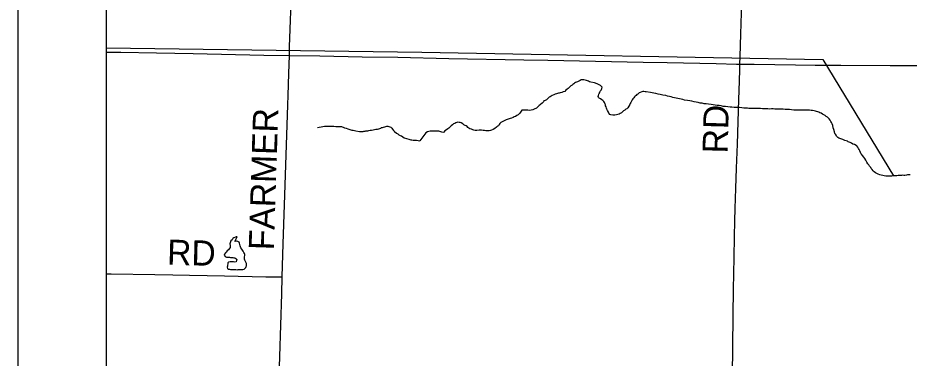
# Model space of a CAD drawing. Extents: x 2.1 to 73.9, y 4 to 26.
# Drawn here: x 41.859 to 42.866, y 24.066 to 24.45 of the extents above; entities that cross this region are included whole.
import ezdxf

# ---------------------------------------------------------------- set-up
doc = ezdxf.new("R2010")
doc.units = 0
for name, color, linetype in [('GM_X_County_Road', 7, 'Continuous'), ('GM_X_County_Road_Text', 7, 'Continuous'), ('GM_X_Minor_Lake', 7, 'Continuous'), ('GM_X_Minor_River', 7, 'Continuous'), ('GM_X_Township_Road', 7, 'Continuous'), ('GM_X_Township_Road_Text', 7, 'Continuous'), ('SH_Data', 7, 'Continuous')]:
    doc.layers.add(name, color=color, linetype=linetype)

msp = doc.modelspace()

# ---------------------------------------------------------------- linework, layer by layer
at = {"layer": 'GM_X_County_Road'}
for points in [[(42.1655, 24.4075), (42.1658, 24.4171), (42.1681, 24.4877), (42.1694, 24.5296), (42.17, 24.5508), (42.1704, 24.5638), (42.1708, 24.5793), (42.1721, 24.6176), (42.1738, 24.6704), (42.1758, 24.7347), (42.1765, 24.758), (42.1782, 24.8099), (42.179, 24.8335), (42.1798, 24.8571), (42.1805, 24.8804), (42.1815, 24.9051)], [(41.9585, 24.4114), (41.9748, 24.4111), (42.0152, 24.4103), (42.0566, 24.4096), (42.1367, 24.4079), (42.1655, 24.4075)], [(42.1574, 24.1573), (42.1586, 24.1947), (42.16, 24.2388), (42.1615, 24.2835), (42.1638, 24.3519), (42.164, 24.3622), (42.1649, 24.3873), (42.1655, 24.4075)], [(42.1655, 24.4075), (42.1998, 24.407), (42.2477, 24.4061), (42.2881, 24.4054), (42.3456, 24.4042), (42.4304, 24.4026), (42.4575, 24.4021), (42.5116, 24.401), (42.5653, 24.3999), (42.5924, 24.3995), (42.648, 24.3983), (42.671, 24.3978), (42.6747, 24.3978)], [(42.6747, 24.3978), (42.6909, 24.3975), (42.7375, 24.3969), (42.7599, 24.3967), (42.7888, 24.3967), (42.8445, 24.3963), (42.8746, 24.3962), (42.9104, 24.3959), (42.9561, 24.3954), (42.9819, 24.3952), (43.026, 24.395), (43.0534, 24.3948), (43.0959, 24.3944), (43.1177, 24.3942), (43.1618, 24.3936), (43.1649, 24.3935)], [(42.1493, 23.9037), (42.1497, 23.92), (42.1506, 23.9468), (42.1527, 24.0114), (42.1534, 24.0319), (42.1557, 24.1027), (42.1569, 24.1381), (42.1574, 24.1573)]]:
    msp.add_lwpolyline(points, dxfattribs=at)
at = {"layer": 'GM_X_Minor_Lake'}
msp.add_line((42.104, 24.1975), (42.1063, 24.2027), dxfattribs=at)
msp.add_lwpolyline([(42.1063, 24.2027), (42.1055, 24.2026), (42.1044, 24.2021), (42.1028, 24.2017), (42.1017, 24.2008), (42.1007, 24.1993), (42.0995, 24.198), (42.0989, 24.1971), (42.0985, 24.1958), (42.0982, 24.1947), (42.0986, 24.1928), (42.0987, 24.1916), (42.0985, 24.1905), (42.0973, 24.189), (42.0965, 24.1881), (42.0953, 24.1868), (42.0939, 24.1853), (42.0932, 24.1844), (42.092, 24.1829), (42.0919, 24.1818), (42.093, 24.1804), (42.0943, 24.1798), (42.0955, 24.1796), (42.0968, 24.1795), (42.0979, 24.1795), (42.0991, 24.1794), (42.1002, 24.1794), (42.1014, 24.1794), (42.1027, 24.1791), (42.1038, 24.1789), (42.1051, 24.1781), (42.106, 24.177), (42.1056, 24.1758), (42.1052, 24.1743), (42.1039, 24.174), (42.1022, 24.1744), (42.1008, 24.1745), (42.0997, 24.1745), (42.0984, 24.1745), (42.0968, 24.174), (42.096, 24.1731), (42.0958, 24.1721), (42.0956, 24.1708), (42.0955, 24.1697), (42.0953, 24.1682), (42.0955, 24.1668), (42.0964, 24.1662), (42.0977, 24.166), (42.099, 24.1658), (42.1002, 24.1657), (42.1013, 24.1657), (42.1026, 24.1657), (42.104, 24.1656), (42.1051, 24.1656), (42.1064, 24.1655), (42.1076, 24.1657), (42.1087, 24.1657), (42.1102, 24.1656), (42.1114, 24.1656), (42.1129, 24.1659), (42.1143, 24.1661), (42.115, 24.167), (42.1162, 24.1681), (42.1168, 24.169), (42.117, 24.17), (42.1171, 24.1709), (42.1169, 24.1726), (42.1164, 24.174), (42.1159, 24.1749), (42.1152, 24.1763), (42.1148, 24.1774), (42.1147, 24.179), (42.1149, 24.1801), (42.1151, 24.1814), (42.115, 24.1826), (42.1148, 24.1837), (42.1141, 24.1851), (42.1132, 24.1864), (42.1125, 24.1874), (42.1117, 24.1887), (42.1108, 24.1901), (42.1101, 24.1913), (42.11, 24.1924), (42.1091, 24.1955), (42.1086, 24.1966), (42.1071, 24.1974), (42.1056, 24.1977), (42.1046, 24.1977), (42.104, 24.1975)], dxfattribs=at)
msp.add_lwpolyline([(42.1063, 24.2027), (42.1055, 24.2026), (42.1044, 24.2021), (42.1028, 24.2017), (42.1017, 24.2008), (42.1007, 24.1993), (42.0995, 24.198), (42.0989, 24.1971), (42.0985, 24.1958), (42.0982, 24.1947), (42.0986, 24.1928), (42.0987, 24.1916), (42.0985, 24.1905), (42.0973, 24.189), (42.0965, 24.1881), (42.0953, 24.1868), (42.0939, 24.1853), (42.0932, 24.1844), (42.092, 24.1829), (42.0919, 24.1818), (42.093, 24.1804), (42.0943, 24.1798), (42.0955, 24.1796), (42.0968, 24.1795), (42.0979, 24.1795), (42.0991, 24.1794), (42.1002, 24.1794), (42.1014, 24.1794), (42.1027, 24.1791), (42.1038, 24.1789), (42.1051, 24.1781), (42.106, 24.177), (42.1056, 24.1758), (42.1052, 24.1743), (42.1039, 24.174), (42.1022, 24.1744), (42.1008, 24.1745), (42.0997, 24.1745), (42.0984, 24.1745), (42.0968, 24.174), (42.096, 24.1731), (42.0958, 24.1721), (42.0956, 24.1708), (42.0955, 24.1697), (42.0953, 24.1682), (42.0955, 24.1668), (42.0964, 24.1662), (42.0977, 24.166), (42.099, 24.1658), (42.1002, 24.1657), (42.1013, 24.1657), (42.1026, 24.1657), (42.104, 24.1656), (42.1051, 24.1656), (42.1064, 24.1655), (42.1076, 24.1657), (42.1087, 24.1657), (42.1102, 24.1656), (42.1114, 24.1656), (42.1129, 24.1659), (42.1143, 24.1661), (42.115, 24.167), (42.1162, 24.1681), (42.1168, 24.169), (42.117, 24.17), (42.1171, 24.1709), (42.1169, 24.1726), (42.1164, 24.174), (42.1159, 24.1749), (42.1152, 24.1763), (42.1148, 24.1774), (42.1147, 24.179), (42.1149, 24.1801), (42.1151, 24.1814), (42.115, 24.1826), (42.1148, 24.1837), (42.1141, 24.1851), (42.1132, 24.1864), (42.1125, 24.1874), (42.1117, 24.1887), (42.1108, 24.1901), (42.1101, 24.1913), (42.11, 24.1924), (42.1091, 24.1955), (42.1086, 24.1966), (42.1071, 24.1974), (42.1056, 24.1977), (42.1046, 24.1977), (42.104, 24.1975)], dxfattribs=at)
at = {"layer": 'GM_X_Minor_River'}
msp.add_line((41.9585, 24.4163), (42.3154, 24.4112), dxfattribs=at)
for points in [[(42.3154, 24.4112), (42.7684, 24.4028), (42.8485, 24.2714)], [(42.5216, 24.3544), (42.5208, 24.3556), (42.5197, 24.3566), (42.5186, 24.3575), (42.5171, 24.3585), (42.5157, 24.3593), (42.5148, 24.3599), (42.5146, 24.361), (42.5148, 24.3621), (42.5154, 24.3637), (42.5158, 24.3646), (42.5164, 24.3657), (42.5168, 24.3671), (42.5178, 24.3682), (42.5182, 24.3691), (42.5186, 24.3703), (42.5192, 24.3716), (42.5182, 24.3725), (42.5173, 24.3735), (42.5158, 24.3743), (42.5149, 24.3747), (42.5135, 24.3753), (42.5124, 24.3759), (42.5115, 24.3763), (42.5105, 24.3765), (42.5061, 24.3773), (42.5048, 24.3779), (42.5035, 24.3783), (42.5024, 24.3787), (42.5012, 24.3791), (42.4997, 24.3797), (42.4984, 24.3799), (42.4972, 24.3801), (42.4963, 24.3801), (42.4953, 24.3799), (42.4942, 24.3794), (42.4927, 24.3786), (42.4911, 24.3779), (42.489, 24.3768), (42.4879, 24.3761), (42.4869, 24.3755), (42.4859, 24.3748), (42.485, 24.3738), (42.4838, 24.3731), (42.4829, 24.3723), (42.4819, 24.3712), (42.4805, 24.3703), (42.4794, 24.3694), (42.478, 24.3682), (42.4767, 24.3669), (42.475, 24.3664), (42.4734, 24.3657), (42.4715, 24.3653), (42.4706, 24.3649), (42.4696, 24.3648), (42.4685, 24.3644), (42.4673, 24.364), (42.466, 24.3637), (42.4646, 24.3631), (42.4627, 24.3624), (42.4616, 24.3615), (42.4602, 24.3609), (42.4593, 24.3604), (42.4579, 24.3593), (42.457, 24.3581), (42.456, 24.3574), (42.4545, 24.3568), (42.4533, 24.3563), (42.4527, 24.3553), (42.4514, 24.3538), (42.4498, 24.3524), (42.4489, 24.3516), (42.4479, 24.3509), (42.4466, 24.3497), (42.4448, 24.3481), (42.4423, 24.347), (42.4406, 24.3462), (42.4389, 24.3459), (42.437, 24.3455), (42.4349, 24.3456), (42.4328, 24.3456), (42.4309, 24.3458), (42.4296, 24.3458), (42.4284, 24.3457), (42.4269, 24.3434), (42.4255, 24.3419), (42.4242, 24.3406), (42.4226, 24.3397), (42.4211, 24.3387), (42.4197, 24.338), (42.4184, 24.3373), (42.4167, 24.3367), (42.415, 24.3362), (42.4129, 24.3357), (42.4106, 24.3347), (42.4081, 24.3338), (42.4062, 24.3327), (42.4046, 24.3318), (42.4035, 24.3307), (42.4025, 24.3295), (42.4017, 24.3282)], [(42.7023, 24.3474), (42.7004, 24.3474), (42.6981, 24.3475), (42.6957, 24.3475), (42.6924, 24.3476), (42.6864, 24.3477), (42.6848, 24.3477), (42.6833, 24.3479), (42.6814, 24.3479), (42.6793, 24.3481), (42.677, 24.3484), (42.6744, 24.3486), (42.6719, 24.3488), (42.6683, 24.3489), (42.6658, 24.3491), (42.6636, 24.3492), (42.6611, 24.3494), (42.6586, 24.3498), (42.656, 24.35), (42.6537, 24.3505), (42.6514, 24.3509), (42.6491, 24.3511), (42.6467, 24.3515), (42.6444, 24.3519), (42.6421, 24.3523), (42.6391, 24.3526), (42.6368, 24.3528), (42.6345, 24.353), (42.632, 24.3535), (42.6298, 24.3537), (42.6275, 24.3543), (42.6252, 24.3547), (42.6229, 24.3551), (42.6205, 24.3557), (42.618, 24.3561), (42.6154, 24.3568), (42.6123, 24.3572), (42.6102, 24.3576), (42.6083, 24.358), (42.6065, 24.3584), (42.6046, 24.3588), (42.6027, 24.3592), (42.6008, 24.3596), (42.5989, 24.3602), (42.597, 24.3607), (42.5951, 24.3611), (42.593, 24.3615), (42.5909, 24.3621), (42.5877, 24.3627), (42.5848, 24.3633), (42.5822, 24.3639), (42.5797, 24.3645), (42.5776, 24.365), (42.5756, 24.3654), (42.5737, 24.3658), (42.5687, 24.3666), (42.5676, 24.3666), (42.5663, 24.3667), (42.5651, 24.3667), (42.5638, 24.3663), (42.5621, 24.3658), (42.5609, 24.3652), (42.5592, 24.3639), (42.5582, 24.3634), (42.5574, 24.3624), (42.5563, 24.3617), (42.5555, 24.3607), (42.5547, 24.3596), (42.5538, 24.3585), (42.553, 24.3574), (42.5522, 24.3559), (42.5514, 24.3545), (42.5508, 24.3534), (42.5502, 24.3523), (42.5491, 24.3502), (42.5479, 24.3483), (42.5469, 24.3474), (42.5458, 24.3467), (42.5446, 24.3457), (42.5431, 24.3448), (42.5419, 24.3439), (42.5408, 24.3427), (42.5394, 24.342), (42.5383, 24.3413), (42.5368, 24.3407), (42.5354, 24.3404), (42.5333, 24.3402), (42.5312, 24.3402), (42.5289, 24.3405), (42.5278, 24.3409), (42.5267, 24.3424), (42.5261, 24.3435), (42.525, 24.3453), (42.5243, 24.347), (42.5239, 24.3479), (42.5236, 24.3495), (42.523, 24.3506), (42.5229, 24.3516), (42.5225, 24.3525), (42.5219, 24.3535), (42.5216, 24.3544)], [(42.8485, 24.2714), (42.8472, 24.2714), (42.8462, 24.2712), (42.8453, 24.2712), (42.8441, 24.2713), (42.8428, 24.2711), (42.8413, 24.2711), (42.8398, 24.2713), (42.838, 24.2715), (42.8329, 24.2728), (42.8312, 24.2734), (42.8297, 24.2741), (42.8282, 24.2751), (42.8267, 24.2759), (42.8254, 24.2773), (42.8243, 24.2786), (42.8233, 24.2798), (42.8226, 24.2811), (42.8213, 24.2824), (42.8204, 24.2838), (42.8194, 24.2851), (42.8183, 24.2869), (42.8172, 24.2892), (42.8159, 24.2911), (42.8148, 24.2926), (42.8135, 24.2945), (42.8124, 24.2959), (42.8116, 24.2968), (42.8111, 24.298), (42.8102, 24.2999), (42.8094, 24.3013), (42.8089, 24.3026), (42.8079, 24.3039), (42.807, 24.3053), (42.8061, 24.3059), (42.8042, 24.3068), (42.8025, 24.3074), (42.8008, 24.3084), (42.7993, 24.3092), (42.7983, 24.3096), (42.7972, 24.31), (42.7963, 24.3106), (42.7947, 24.3112), (42.7932, 24.3116), (42.7913, 24.3124), (42.7898, 24.3128), (42.7887, 24.3132), (42.7876, 24.3136), (42.7866, 24.314), (42.7853, 24.3149), (42.784, 24.3165), (42.7834, 24.3174), (42.7829, 24.3186), (42.7821, 24.3195), (42.7816, 24.3211), (42.7809, 24.3239), (42.7803, 24.3256), (42.7798, 24.3283), (42.7791, 24.3304), (42.7783, 24.3319), (42.7776, 24.3331), (42.7767, 24.3344), (42.7757, 24.3358), (42.7746, 24.3369), (42.7737, 24.3377), (42.7724, 24.3387), (42.771, 24.3397), (42.7697, 24.3404), (42.7682, 24.3412), (42.7665, 24.3422), (42.7652, 24.3428), (42.7641, 24.3434), (42.7627, 24.3438), (42.7614, 24.3442), (42.7601, 24.3446), (42.7586, 24.345), (42.7569, 24.3452), (42.7552, 24.3454), (42.7535, 24.3456), (42.7517, 24.3457), (42.7495, 24.3459), (42.7462, 24.3458), (42.7436, 24.3458), (42.7407, 24.3458), (42.7381, 24.3459), (42.7356, 24.3459), (42.7331, 24.3462), (42.7308, 24.3464), (42.7286, 24.3464), (42.7261, 24.3466), (42.7238, 24.3467), (42.7215, 24.3467), (42.7187, 24.347), (42.7166, 24.347), (42.7143, 24.347), (42.7124, 24.3471), (42.7103, 24.3471), (42.7084, 24.3469), (42.7063, 24.3471), (42.7044, 24.3474), (42.7023, 24.3474)], [(42.1971, 24.3263), (42.1992, 24.3267), (42.2015, 24.327), (42.2034, 24.3273), (42.2053, 24.3276), (42.2074, 24.3278), (42.2095, 24.3277), (42.212, 24.3276), (42.2139, 24.3276), (42.2158, 24.3275), (42.2181, 24.3274), (42.2203, 24.3274), (42.222, 24.3273), (42.2234, 24.3273), (42.2243, 24.3272), (42.2253, 24.3268), (42.2264, 24.3264), (42.2279, 24.3258), (42.2298, 24.3252), (42.2317, 24.3247), (42.2328, 24.3243), (42.2339, 24.3237), (42.235, 24.3235), (42.236, 24.3233), (42.2375, 24.323), (42.2392, 24.3228), (42.2407, 24.3222), (42.2449, 24.3218), (42.246, 24.3216), (42.2479, 24.3217), (42.2489, 24.3217), (42.2498, 24.3219), (42.251, 24.322), (42.2521, 24.3222), (42.2531, 24.3223), (42.254, 24.3225), (42.2552, 24.3227), (42.2569, 24.323), (42.2584, 24.3231), (42.2603, 24.3234), (42.2619, 24.3238), (42.2634, 24.3241), (42.2651, 24.3244), (42.2667, 24.3248), (42.2676, 24.3251), (42.2688, 24.3255), (42.2697, 24.326), (42.2709, 24.3263), (42.272, 24.3267), (42.2734, 24.327), (42.2747, 24.3274), (42.2757, 24.3275), (42.2766, 24.3275), (42.278, 24.3273), (42.2789, 24.3269), (42.28, 24.3264), (42.2813, 24.3253), (42.282, 24.3243), (42.2831, 24.3229), (42.2844, 24.3216), (42.2865, 24.3198), (42.288, 24.3188), (42.2893, 24.3178), (42.2906, 24.3172), (42.2923, 24.3166), (42.2937, 24.3156), (42.2954, 24.3146), (42.3007, 24.3129), (42.3026, 24.3123), (42.3041, 24.3122), (42.3056, 24.312), (42.3067, 24.3117), (42.3077, 24.3117), (42.3092, 24.3119), (42.313, 24.3111)], [(42.4017, 24.3282), (42.4007, 24.3275), (42.3996, 24.3264), (42.3977, 24.3249), (42.3959, 24.3238), (42.394, 24.3232), (42.3927, 24.3229), (42.3913, 24.3225), (42.39, 24.3223), (42.3889, 24.3224), (42.3877, 24.3224), (42.3862, 24.3226), (42.3847, 24.3228), (42.3826, 24.3232), (42.3801, 24.3231), (42.3773, 24.3229), (42.3756, 24.3229), (42.374, 24.3232), (42.3727, 24.3236), (42.3712, 24.3242), (42.3695, 24.3248), (42.3682, 24.3255), (42.3673, 24.3263), (42.3663, 24.3271), (42.3652, 24.3279), (42.3641, 24.3284), (42.3627, 24.329), (42.3616, 24.3302), (42.3597, 24.3314), (42.3586, 24.3318), (42.3573, 24.3318), (42.3559, 24.332), (42.3548, 24.3318), (42.3536, 24.3313), (42.3525, 24.3307), (42.3511, 24.3302), (42.3498, 24.3292), (42.3484, 24.3279), (42.3469, 24.3264), (42.3456, 24.3255), (42.3446, 24.3246), (42.3432, 24.3235), (42.3411, 24.3222), (42.34, 24.321), (42.3388, 24.3205), (42.3366, 24.3213), (42.3343, 24.3219), (42.332, 24.3219), (42.3297, 24.322), (42.3274, 24.322), (42.3259, 24.322), (42.3246, 24.3219), (42.3231, 24.3217), (42.3215, 24.3211), (42.3198, 24.3202), (42.313, 24.3111)], [(42.8674, 24.2728), (42.866, 24.2726), (42.8643, 24.2725), (42.863, 24.2723), (42.8613, 24.2721), (42.8599, 24.2721), (42.8586, 24.2722), (42.8573, 24.272), (42.8559, 24.272), (42.8546, 24.272), (42.8535, 24.2719), (42.8521, 24.2717), (42.8508, 24.2717), (42.8495, 24.2716), (42.8485, 24.2714)]]:
    msp.add_lwpolyline(points, dxfattribs=at)
at = {"layer": 'GM_X_Township_Road'}
for points in [[(42.6747, 24.3978), (42.675, 24.4064), (42.6758, 24.4316), (42.6773, 24.4801), (42.6778, 24.499), (42.6786, 24.5313), (42.6791, 24.5444), (42.6796, 24.5599), (42.6801, 24.5782), (42.6814, 24.6314), (42.6822, 24.6652), (42.6827, 24.6941), (42.6834, 24.7224), (42.6839, 24.7563), (42.6842, 24.769), (42.6843, 24.7852), (42.6845, 24.8044), (42.6847, 24.8249), (42.685, 24.8433), (42.6853, 24.8576), (42.6859, 24.889), (42.686, 24.9038)], [(42.6642, 23.8935), (42.6645, 23.9112), (42.6648, 23.9363), (42.6654, 23.9724), (42.6657, 23.9982), (42.6661, 24.0215), (42.6665, 24.0464), (42.6668, 24.0778), (42.6673, 24.1141), (42.6675, 24.1433), (42.6681, 24.1794), (42.6687, 24.2027), (42.6692, 24.2207), (42.6695, 24.2347), (42.6702, 24.2574), (42.6709, 24.2801), (42.6719, 24.3074), (42.6734, 24.3577), (42.6742, 24.3785), (42.6746, 24.3916), (42.6747, 24.3978)], [(41.9585, 24.1609), (41.9639, 24.1608), (42.0134, 24.1601), (42.0336, 24.1597), (42.0525, 24.1594), (42.0724, 24.1589), (42.092, 24.1586), (42.1389, 24.1576), (42.1574, 24.1573)]]:
    msp.add_lwpolyline(points, dxfattribs=at)
at = {"layer": 'SH_Data'}
for p, q in [((41.8585, 25.0051), (41.8585, 18.0051)), ((41.9585, 24.9051), (41.9585, 18.1051))]:
    msp.add_line(p, q, dxfattribs=at)

# ---------------------------------------------------------------- texts
at = {"layer": 'GM_X_County_Road_Text'}
msp.add_text('FARMER', height=0.02841, rotation=88.1684, dxfattribs=at).set_placement((42.1479, 24.1872))
at = {"layer": 'GM_X_Township_Road_Text'}
for rotation, p in [(88.5377, (42.6609, 24.2966)), (358.5191, (42.027, 24.1712))]:
    msp.add_text('RD', height=0.02841, rotation=rotation, dxfattribs=at).set_placement(p)

doc.saveas('drawing.dxf')
